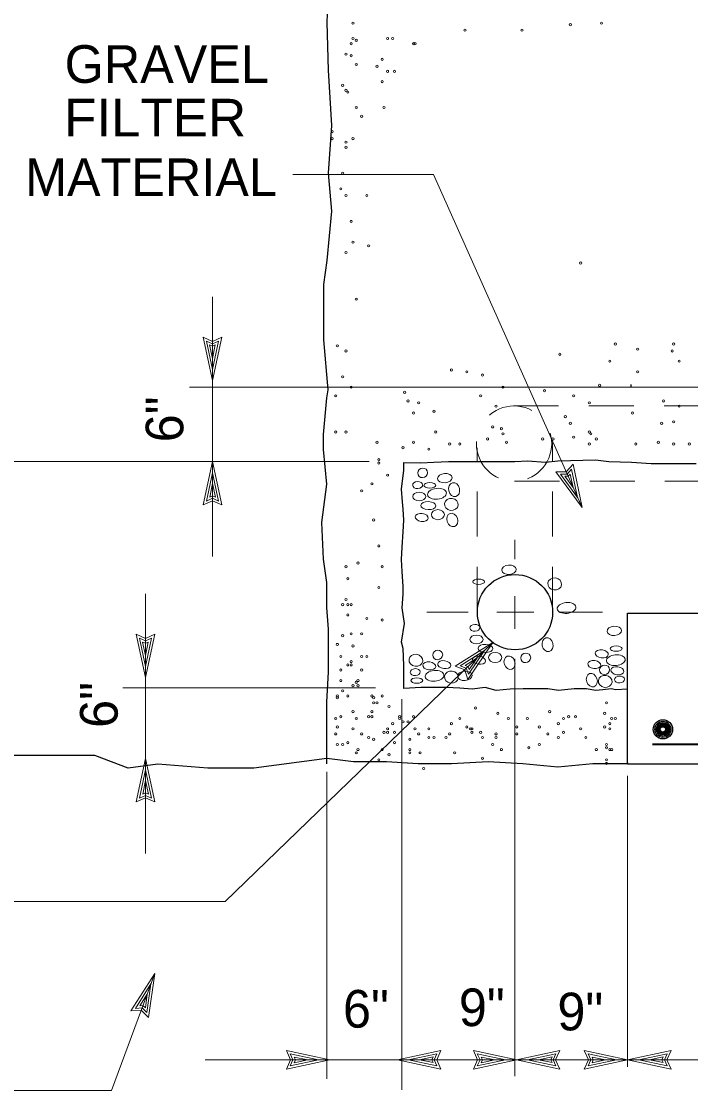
# Model space of a CAD drawing. Extents: x -24.3 to 17.7, y -17.6 to 12.4.
# Drawn here: x -19.213 to -16.992, y -13.602 to -10.053 of the extents above; entities that cross this region are included whole.
import ezdxf
from ezdxf.enums import TextEntityAlignment as Align

# ---------------------------------------------------------------- set-up
doc = ezdxf.new("R2010")
doc.units = 0
doc.header["$LTSCALE"] = 0.05
doc.linetypes.add('MEDIUM_DASHED', pattern=[4.5, 3, -1.5])
doc.layers.add('1', color=7, linetype='Continuous', lineweight=13)

msp = doc.modelspace()

# ---------------------------------------------------------------- linework, layer by layer
at = {"layer": '1'}
for p, q in [((-18.57869, -11.2446), (-18.60969, -11.1006)), ((-18.57869, -11.2446), (-18.54769, -11.1006)), ((-18.57869, -11.2076), (-18.59869, -11.1136)), ((-18.59869, -11.1136), (-18.57869, -11.1226)), ((-18.57869, -11.1716), (-18.58869, -11.1266)), ((-18.58869, -11.1266), (-18.57869, -11.1306)), ((-18.57869, -11.2076), (-18.55869, -11.1136)), ((-18.57869, -11.1226), (-18.55869, -11.1136)), ((-18.57869, -11.1716), (-18.56969, -11.1266)), ((-18.57869, -11.1306), (-18.56969, -11.1266)), ((-16.59669, -11.2666), (-18.65469, -11.2666)), ((-18.05869, -11.5136), (-19.44569, -11.5136)), ((-18.57869, -11.5136), (-18.60969, -11.6576)), ((-18.57869, -11.5136), (-18.54769, -11.6576)), ((-17.35169, -11.6666), (-17.38169, -11.5226)), ((-18.57869, -11.5506), (-18.59869, -11.6446)), ((-18.57869, -11.5506), (-18.55869, -11.6446)), ((-17.36669, -11.6326), (-17.42369, -11.5556)), ((-17.42369, -11.5556), (-17.40169, -11.5556)), ((-17.38169, -11.5996), (-17.40869, -11.5626)), ((-17.40869, -11.5626), (-17.39769, -11.5626)), ((-17.40169, -11.5556), (-17.38669, -11.5386)), ((-17.39769, -11.5626), (-17.39169, -11.5556)), ((-17.38169, -11.5996), (-17.39169, -11.5556)), ((-17.36669, -11.6326), (-17.38669, -11.5386)), ((-18.57869, -11.5866), (-18.58769, -11.6316)), ((-18.57869, -11.5866), (-18.56869, -11.6316)), ((-18.57869, -11.6356), (-18.59869, -11.6446)), ((-18.57869, -11.6276), (-18.58769, -11.6316)), ((-18.56869, -11.6316), (-18.57869, -11.6276)), ((-18.55869, -11.6446), (-18.57869, -11.6356)), ((-17.57569, -11.8376), (-17.57569, -11.7736)), ((-17.57569, -12.0686), (-17.57569, -11.9606)), ((-17.86769, -12.0136), (-17.72969, -12.0136)), ((-17.63469, -12.0136), (-17.51169, -12.0136)), ((-17.42869, -12.0136), (-17.28469, -12.0136)), ((-18.80169, -12.2306), (-18.83269, -12.0866)), ((-18.80169, -12.1936), (-18.82169, -12.0996)), ((-18.82169, -12.0996), (-18.80169, -12.1086)), ((-18.80169, -12.2306), (-18.77069, -12.0866)), ((-18.80169, -12.1936), (-18.78169, -12.0996)), ((-18.80169, -12.1086), (-18.78169, -12.0996)), ((-18.80169, -12.1576), (-18.81169, -12.1126)), ((-18.81169, -12.1126), (-18.80169, -12.1166)), ((-18.80169, -12.1576), (-18.79269, -12.1126)), ((-18.80169, -12.1166), (-18.79269, -12.1126)), ((-17.64869, -12.1146), (-17.77369, -12.1926)), ((-17.67569, -12.1406), (-17.75669, -12.1916)), ((-17.70069, -12.1656), (-17.73969, -12.1906)), ((-17.67569, -12.1406), (-17.72869, -12.2196)), ((-17.70069, -12.1656), (-17.72669, -12.2036)), ((-17.57569, -13.5536), (-17.57569, -12.1686)), ((-17.73669, -12.1996), (-17.75669, -12.1916)), ((-17.73069, -12.1936), (-17.73969, -12.1906)), ((-17.72869, -12.2196), (-17.73669, -12.1996)), ((-17.72669, -12.2036), (-17.73069, -12.1936)), ((-18.03769, -12.2646), (-18.87669, -12.2646)), ((-17.95069, -13.5986), (-17.95069, -12.3026)), ((-18.80169, -12.4996), (-18.83269, -12.6436)), ((-18.80169, -12.4996), (-18.77069, -12.6436)), ((-18.80169, -12.5366), (-18.82169, -12.6306)), ((-18.80169, -12.5366), (-18.78169, -12.6306)), ((-18.19969, -13.5626), (-18.19969, -12.5436)), ((-17.20069, -13.5226), (-17.20069, -12.5566)), ((-18.80169, -12.5726), (-18.81069, -12.6176)), ((-18.80169, -12.5726), (-18.79169, -12.6176)), ((-18.80169, -12.6216), (-18.82169, -12.6306)), ((-18.80169, -12.6136), (-18.81069, -12.6176)), ((-18.79169, -12.6176), (-18.80169, -12.6136)), ((-18.78169, -12.6306), (-18.80169, -12.6216)), ((-18.77069, -13.2126), (-18.84969, -13.3366)), ((-18.78369, -13.2476), (-18.83469, -13.3286)), ((-18.78369, -13.2476), (-18.79669, -13.3426)), ((-18.79569, -13.2816), (-18.81969, -13.3206)), ((-18.79569, -13.2816), (-18.80169, -13.3266)), ((-18.81269, -13.3266), (-18.83469, -13.3286)), ((-18.80969, -13.3196), (-18.81969, -13.3206)), ((-18.79669, -13.3426), (-18.81269, -13.3266)), ((-18.80169, -13.3266), (-18.80969, -13.3196)), ((-18.18969, -13.4996), (-18.33369, -13.4686)), ((-18.22669, -13.4996), (-18.32069, -13.4796)), ((-18.31169, -13.4996), (-18.32069, -13.4796)), ((-17.96469, -13.4996), (-17.82069, -13.4686)), ((-17.92769, -13.4996), (-17.83369, -13.4796)), ((-17.83369, -13.4796), (-17.84269, -13.4996)), ((-17.56869, -13.4996), (-17.71269, -13.4686)), ((-17.60569, -13.4996), (-17.69969, -13.4796)), ((-17.69069, -13.4996), (-17.69969, -13.4796)), ((-17.56969, -13.4996), (-17.42569, -13.4686)), ((-17.53269, -13.4996), (-17.43869, -13.4796)), ((-17.43869, -13.4796), (-17.44769, -13.4996)), ((-17.20069, -13.4996), (-17.34469, -13.4686)), ((-17.23769, -13.4996), (-17.33169, -13.4796)), ((-17.32269, -13.4996), (-17.33169, -13.4796)), ((-17.20069, -13.4996), (-17.05669, -13.4686)), ((-17.16369, -13.4996), (-17.06969, -13.4796)), ((-17.06969, -13.4796), (-17.07869, -13.4996)), ((-18.60369, -13.4996), (-18.18969, -13.4996)), ((-18.18969, -13.4996), (-18.33369, -13.5306)), ((-18.22669, -13.4996), (-18.32069, -13.5196)), ((-18.32069, -13.5196), (-18.31169, -13.4996)), ((-18.26269, -13.4996), (-18.30769, -13.4906)), ((-18.30369, -13.4996), (-18.30769, -13.4906)), ((-18.26269, -13.4996), (-18.30769, -13.5096)), ((-18.30769, -13.5096), (-18.30369, -13.4996)), ((-18.19569, -13.4996), (-17.96469, -13.4996)), ((-17.96469, -13.4996), (-17.56869, -13.4996)), ((-17.96469, -13.4996), (-17.82069, -13.5306)), ((-17.92769, -13.4996), (-17.83369, -13.5196)), ((-17.89169, -13.4996), (-17.84669, -13.4896)), ((-17.89169, -13.4996), (-17.84669, -13.5086)), ((-17.84669, -13.4896), (-17.85069, -13.4996)), ((-17.85069, -13.4996), (-17.84669, -13.5086)), ((-17.84269, -13.4996), (-17.83369, -13.5196)), ((-17.56869, -13.4996), (-17.71269, -13.5306)), ((-17.60569, -13.4996), (-17.69969, -13.5196)), ((-17.69969, -13.5196), (-17.69069, -13.4996)), ((-17.64169, -13.4996), (-17.68669, -13.4906)), ((-17.68269, -13.4996), (-17.68669, -13.4906)), ((-17.64169, -13.4996), (-17.68669, -13.5096)), ((-17.68669, -13.5096), (-17.68269, -13.4996)), ((-17.56969, -13.4996), (-17.20069, -13.4996)), ((-17.56969, -13.4996), (-17.42569, -13.5306)), ((-17.53269, -13.4996), (-17.43869, -13.5196)), ((-17.49669, -13.4996), (-17.45169, -13.4896)), ((-17.49669, -13.4996), (-17.45169, -13.5086)), ((-17.45169, -13.4896), (-17.45569, -13.4996)), ((-17.45569, -13.4996), (-17.45169, -13.5086)), ((-17.44769, -13.4996), (-17.43869, -13.5196)), ((-17.20069, -13.4996), (-17.34469, -13.5306)), ((-17.23769, -13.4996), (-17.33169, -13.5196)), ((-17.33169, -13.5196), (-17.32269, -13.4996)), ((-17.27369, -13.4996), (-17.31869, -13.4906)), ((-17.31469, -13.4996), (-17.31869, -13.4906)), ((-17.27369, -13.4996), (-17.31869, -13.5096)), ((-17.31869, -13.5096), (-17.31469, -13.4996)), ((-17.20069, -13.4996), (-17.05669, -13.5306)), ((-17.16369, -13.4996), (-17.06969, -13.5196)), ((-17.12769, -13.4996), (-17.08269, -13.4896)), ((-17.12769, -13.4996), (-17.08269, -13.5086)), ((-17.08269, -13.4896), (-17.08669, -13.4996)), ((-17.08669, -13.4996), (-17.08269, -13.5086)), ((-17.07869, -13.4996), (-17.06969, -13.5196)), ((-19.30869, -13.6016), (-18.91369, -13.6016))]:
    msp.add_line(p, q, dxfattribs=at)
at = {"layer": '1', "lineweight": 25}
for p, q in [((-17.18969, -11.2576), (-17.18969, -11.2646)), ((-17.20069, -12.0166), (-15.57569, -12.0166)), ((-17.20069, -12.5166), (-17.20069, -12.0166))]:
    msp.add_line(p, q, dxfattribs=at)
at = {"layer": '1', "linetype": 'MEDIUM_DASHED'}
for p, q in [((-17.57969, -11.3286), (-16.55969, -11.3286)), ((-17.44969, -12.0126), (-17.44969, -11.4516)), ((-17.69969, -12.0126), (-17.69969, -11.4686)), ((-17.57669, -11.5786), (-16.69969, -11.5786))]:
    msp.add_line(p, q, dxfattribs=at)
at = {"layer": '1', "lineweight": 35}
msp.add_line((-16.18569, -12.4526), (-17.11869, -12.4526), dxfattribs=at)
at = {"layer": '1', "lineweight": 25}
for points in [[(-18.19969, -12.4996), (-18.44169, -12.5316), (-18.59469, -12.5316), (-18.76069, -12.5176), (-18.85869, -12.5316), (-18.96969, -12.4896), (-19.23369, -12.4896), (-19.35869, -12.4896), (-19.55369, -12.5176), (-19.73469, -12.4896), (-19.92869, -12.4756), (-19.95069, -12.4756), (-19.98469, -12.3086), (-19.97069, -12.0726), (-19.97069, -11.8226), (-19.94269, -11.5586), (-19.97069, -11.3916), (-19.94269, -11.1136), (-19.94269, -10.8626), (-19.94269, -10.7796), (-19.94269, -10.5576), (-19.94269, -10.2796), (-19.94269, -10.0566), (-19.97069, -9.8206)], [(-18.19469, -11.2756), (-18.20969, -11.1096), (-18.20969, -10.9256), (-18.19869, -10.8466), (-18.18269, -10.6826), (-18.19369, -10.5566), (-18.18269, -10.3986), (-18.19369, -10.2146), (-18.19869, -10.0566), (-18.19369, -9.9406), (-18.19369, -9.8546), (-18.06669, -9.8546), (-17.92469, -9.8456), (-17.73569, -9.8616), (-17.57769, -9.8516), (-17.45169, -9.8456), (-17.34569, -9.8456), (-17.21969, -9.8616), (-17.15169, -9.8676), (-17.07869, -9.8596)], [(-18.19969, -12.5166), (-18.19969, -12.4276), (-18.19969, -12.3506), (-18.19969, -12.3116), (-18.19369, -12.2126), (-18.19369, -12.1686), (-18.19369, -12.0696), (-18.19969, -11.9976), (-18.19969, -11.9146), (-18.21069, -11.8376), (-18.21569, -11.7156), (-18.19969, -11.5886), (-18.21069, -11.4736), (-18.21069, -11.4236), (-18.19969, -11.3026), (-18.19469, -11.2756)], [(-17.20069, -12.2696), (-17.23969, -12.2716), (-17.25569, -12.2676), (-17.28269, -12.2716), (-17.30769, -12.2736), (-17.33769, -12.2676), (-17.37769, -12.2676), (-17.43069, -12.2736), (-17.46569, -12.2676), (-17.50169, -12.2676), (-17.54769, -12.2676), (-17.59069, -12.2696), (-17.63769, -12.2736), (-17.67369, -12.2636), (-17.71669, -12.2696), (-17.75769, -12.2656), (-17.80169, -12.2636), (-17.83269, -12.2636), (-17.88769, -12.2636), (-17.94369, -12.2666), (-17.94369, -12.1906), (-17.94569, -12.1346), (-17.95169, -12.1136), (-17.94169, -12.0516), (-17.94969, -11.9996), (-17.94569, -11.9536), (-17.94569, -11.9286), (-17.94969, -11.8786), (-17.95169, -11.8386), (-17.94969, -11.7976), (-17.94569, -11.7466), (-17.94369, -11.7086), (-17.94569, -11.6716), (-17.94769, -11.6476), (-17.95169, -11.6056), (-17.94369, -11.5426), (-17.94369, -11.5166), (-17.88769, -11.5176), (-17.84369, -11.5156), (-17.79569, -11.5136), (-17.74969, -11.5136), (-17.68669, -11.5136), (-17.63369, -11.5136), (-17.57469, -11.5136), (-17.53169, -11.5116), (-17.47369, -11.5156), (-17.43269, -11.5116), (-17.30769, -11.5076), (-17.26269, -11.5136), (-17.18769, -11.5156), (-17.12269, -11.5196), (-17.06169, -11.5196), (-16.97269, -11.5196)], [(-17.20069, -12.5166), (-15.57569, -12.5166), (-15.57569, -12.0166)], [(-17.20069, -12.5136), (-17.20069, -12.5166), (-17.31669, -12.5166), (-17.43269, -12.5276), (-17.54869, -12.5166), (-17.66369, -12.5106), (-17.78569, -12.5166), (-17.89569, -12.5166), (-18.00069, -12.5106), (-18.11069, -12.5106), (-18.19969, -12.4996)]]:
    msp.add_lwpolyline(points, dxfattribs=at)
at = {"layer": '1'}
for points in [[(-18.31169, -10.5606), (-17.84569, -10.5606), (-17.35169, -11.6666), (-17.43869, -11.5476)], [(-18.57869, -11.8286), (-18.57869, -11.5136), (-18.57869, -11.2446), (-18.57869, -10.9666)], [(-18.60969, -11.1006), (-18.57869, -11.1146), (-18.54769, -11.1006)], [(-17.43869, -11.5476), (-17.40469, -11.5476), (-17.38169, -11.5226)], [(-18.54769, -11.6576), (-18.57869, -11.6436), (-18.60969, -11.6576)], [(-18.80169, -12.8146), (-18.80169, -12.4996), (-18.80169, -12.2306), (-18.80169, -11.9526)], [(-18.83269, -12.0866), (-18.80169, -12.1006), (-18.77069, -12.0866)], [(-19.56469, -12.9736), (-18.53669, -12.9736), (-17.64869, -12.1146), (-17.73069, -12.2366)], [(-17.73069, -12.2366), (-17.74169, -12.2046), (-17.77369, -12.1926)], [(-18.77069, -12.6436), (-18.80169, -12.6296), (-18.83269, -12.6436)], [(-18.91469, -13.6016), (-18.77069, -13.2126), (-18.79169, -13.3586)], [(-18.79169, -13.3586), (-18.81569, -13.3346), (-18.84969, -13.3366)], [(-18.33369, -13.5306), (-18.31969, -13.4996), (-18.33369, -13.4686)], [(-17.82069, -13.4686), (-17.83469, -13.4996), (-17.82069, -13.5306)], [(-17.71269, -13.5306), (-17.69869, -13.4996), (-17.71269, -13.4686)], [(-17.42569, -13.4686), (-17.43969, -13.4996), (-17.42569, -13.5306)], [(-17.34469, -13.5306), (-17.33069, -13.4996), (-17.34469, -13.4686)], [(-17.05669, -13.4686), (-17.07069, -13.4996), (-17.05669, -13.5306)], [(-17.20069, -13.4996), (-16.70069, -13.4996), (-16.07569, -13.4996)]]:
    msp.add_lwpolyline(points, dxfattribs=at)
for centre in [(-18.11269, -10.0586), (-17.74069, -10.0816), (-17.55169, -10.0816), (-17.39069, -10.0636), (-17.28769, -10.0586), (-18.11269, -10.1096), (-18.10169, -10.1156), (-17.99769, -10.1096), (-17.98069, -10.1096), (-18.11869, -10.1266), (-17.91169, -10.1266), (-17.90669, -10.1266), (-18.13569, -10.1616), (-18.11869, -10.1666), (-18.01569, -10.1786), (-18.10169, -10.1956), (-18.03269, -10.2016), (-17.99769, -10.2186), (-17.97469, -10.2186), (-18.01569, -10.2526), (-18.14669, -10.2646), (-18.13569, -10.2816), (-18.12969, -10.2876), (-18.10169, -10.3386), (-18.00969, -10.3386), (-18.08369, -10.3676), (-18.18169, -10.4186), (-18.18169, -10.4416), (-18.13569, -10.4536), (-18.13569, -10.4706), (-18.11269, -10.4416), (-18.14669, -10.5566), (-18.15269, -10.6086), (-18.13569, -10.6306), (-18.06669, -10.6306), (-18.11869, -10.7166), (-18.11269, -10.7856), (-18.13569, -10.8196), (-18.06069, -10.7976), (-17.35669, -10.8546), (-18.10169, -10.9746), (-18.16469, -11.1296), (-18.13569, -11.1466), (-17.24169, -11.1236), (-17.16769, -11.1406), (-17.05269, -11.1466), (-17.04769, -11.1236), (-17.42569, -11.1576), (-17.25969, -11.1806), (-17.02969, -11.1806), (-17.78569, -11.2096), (-17.73469, -11.2156), (-17.16769, -11.2156), (-18.14669, -11.2326), (-18.14669, -11.2326), (-17.68269, -11.2266), (-18.11869, -11.2666), (-17.94069, -11.2836), (-17.61469, -11.2666), (-17.47669, -11.2786), (-17.29369, -11.2606), (-18.16969, -11.2956), (-17.92969, -11.3126), (-17.89469, -11.3186), (-17.68869, -11.2956), (-17.37969, -11.2956), (-17.32769, -11.3186), (-17.08169, -11.3126), (-17.91169, -11.3526), (-17.84369, -11.3466), (-17.63769, -11.3296), (-17.18469, -11.3526), (-17.02969, -11.3296), (-17.40769, -11.3646), (-17.39069, -11.3866), (-17.08769, -11.3866), (-17.04769, -11.3816), (-18.16969, -11.4156), (-18.13569, -11.4156), (-17.83769, -11.4156), (-17.64869, -11.3986), (-17.61969, -11.4046), (-17.61469, -11.4216), (-17.32769, -11.4156), (-17.32269, -11.4216), (-18.03269, -11.4496), (-17.91169, -11.4496), (-17.79169, -11.4556), (-17.75769, -11.4556), (-17.66569, -11.4386), (-17.60269, -11.4496), (-17.48269, -11.4386), (-17.44869, -11.4386), (-17.37969, -11.4326), (-17.32769, -11.4556), (-17.30469, -11.4386), (-17.17369, -11.4556), (-17.09869, -11.4496), (-17.04769, -11.4556), (-16.99569, -11.4556), (-17.94669, -11.4676), (-17.86069, -11.4726), (-18.02669, -11.5076), (-18.02669, -11.5186), (-17.99769, -11.5586), (-18.04969, -11.5876), (-18.08369, -11.6106), (-18.04369, -11.7076), (-18.02669, -11.7936), (-18.09569, -11.8506), (-18.13569, -11.8626), (-18.01569, -11.8626), (-18.12969, -11.9026), (-18.02669, -11.9316), (-18.14669, -11.9886), (-18.13569, -11.9716), (-18.12969, -11.9886), (-18.11869, -11.9886), (-18.12969, -12.0226), (-18.06669, -12.0346), (-18.01569, -12.0396), (-18.14669, -12.0916), (-18.11869, -12.0856), (-18.08369, -12.0856), (-18.16469, -12.1206), (-18.11269, -12.1256), (-18.15269, -12.1606), (-18.08369, -12.1606), (-18.06669, -12.1606), (-18.15269, -12.2056), (-18.12969, -12.1886), (-18.11869, -12.1776), (-18.11869, -12.1886), (-18.08369, -12.2056), (-18.15269, -12.2406), (-18.15269, -12.2406), (-18.10169, -12.2466), (-18.09569, -12.2406), (-18.14669, -12.2746), (-18.11269, -12.2576), (-18.09569, -12.2576), (-18.16469, -12.2916), (-18.16469, -12.2976), (-18.12969, -12.2916), (-18.04969, -12.2916), (-18.04369, -12.2976), (-18.04369, -12.3146), (-18.03269, -12.3146), (-18.01569, -12.2916), (-17.27069, -12.3146), (-18.11269, -12.3436), (-18.04969, -12.3436), (-17.99269, -12.3266), (-17.70569, -12.3316), (-17.63169, -12.3496), (-17.45969, -12.3436), (-17.27669, -12.3496), (-18.16969, -12.3666), (-18.15269, -12.3606), (-18.10169, -12.3666), (-18.06069, -12.3606), (-18.04969, -12.3606), (-17.98069, -12.3836), (-17.95769, -12.3606), (-17.95769, -12.3666), (-17.94669, -12.3776), (-17.92969, -12.3776), (-17.91169, -12.3606), (-17.78569, -12.3836), (-17.75769, -12.3666), (-17.59669, -12.3666), (-17.53369, -12.3666), (-17.43069, -12.3836), (-17.41369, -12.3666), (-17.39669, -12.3606), (-17.37369, -12.3606), (-17.25969, -12.3836), (-17.25369, -12.3666), (-17.24169, -12.3666), (-18.16969, -12.4176), (-18.16469, -12.3946), (-18.11269, -12.4006), (-18.08369, -12.4176), (-18.00969, -12.4126), (-17.99769, -12.4006), (-17.99769, -12.4126), (-17.97469, -12.4126), (-17.90669, -12.4006), (-17.89469, -12.4176), (-17.86069, -12.4006), (-17.79169, -12.4176), (-17.73469, -12.3946), (-17.72269, -12.4006), (-17.71769, -12.4006), (-17.71769, -12.4126), (-17.68869, -12.4126), (-17.63769, -12.4176), (-17.56869, -12.3946), (-17.56869, -12.4176), (-17.49369, -12.3946), (-17.46569, -12.4176), (-17.41369, -12.4126), (-17.35669, -12.4006), (-17.27669, -12.3946), (-17.25969, -12.4006), (-18.16469, -12.4526), (-18.14669, -12.4526), (-18.12969, -12.4466), (-18.06069, -12.4296), (-18.04369, -12.4356), (-17.97469, -12.4466), (-17.92369, -12.4356), (-17.92369, -12.4356), (-17.86069, -12.4296), (-17.84369, -12.4296), (-17.80369, -12.4296), (-17.68269, -12.4296), (-17.64869, -12.4526), (-17.63769, -12.4296), (-17.49369, -12.4526), (-17.43069, -12.4296), (-17.33969, -12.4296), (-17.27069, -12.4526), (-18.10169, -12.4806), (-18.09569, -12.4696), (-18.01569, -12.4696), (-17.99269, -12.4866), (-17.92369, -12.4696), (-17.92369, -12.4806), (-17.88969, -12.4806), (-17.77469, -12.4806), (-17.61969, -12.4696), (-17.52869, -12.4636), (-17.30469, -12.4696), (-17.27069, -12.4636), (-17.25969, -12.4696), (-17.25369, -12.4696), (-18.02669, -12.5036), (-17.68269, -12.4986), (-17.27069, -12.5036), (-17.27069, -12.5156), (-17.87769, -12.5326)]:
    msp.add_circle(centre, 0.00361, dxfattribs=at)
at = {"layer": '1', "linetype": 'MEDIUM_DASHED'}
msp.add_circle((-17.57786, -11.45406), 0.125, dxfattribs=at)
at = {"layer": '1', "lineweight": 25}
for centre, radius in [((-17.57461, -12.01363), 0.125), ((-17.08354, -12.40251), 0.0319), ((-17.08354, -12.40251), 0.02658), ((-17.08354, -12.40251), 0.02215), ((-17.08354, -12.40251), 0.01846), ((-17.08354, -12.40251), 0.01538), ((-17.08354, -12.40251), 0.01282), ((-17.08354, -12.40251), 0.01068), ((-17.08354, -12.40251), 0.0089)]:
    msp.add_circle(centre, radius, dxfattribs=at)
at = {"layer": '1'}
for centre, major_axis, ratio in [((-17.88118, -11.55114), (0.01537, 0.00658), 0.943549), ((-17.80769, -11.56874), (-0.024, -0.00161), 0.646571), ((-17.89775, -11.59153), (0.01656, 0.00102), 0.695424), ((-17.85739, -11.59255), (0.01967, 0), 0.453554), ((-17.83358, -11.62053), (0.03106, 0.0031), 0.576005), ((-17.77662, -11.60705), (0.00519, -0.02279), 0.773526), ((-17.89258, -11.62985), (0.02173, 0), 0.668043), ((-17.78594, -11.6557), (0.02279, -0.0031), 0.872178), ((-17.86256, -11.65984), (0.02483, -0.00104), 0.540552), ((-17.83046, -11.68989), (0.02173, 0), 0.771092), ((-17.88431, -11.6992), (0.02175, -0.0031), 0.60385), ((-17.78285, -11.70749), (0.00725, -0.02173), 0.776129), ((-17.59469, -11.87274), (-0.024, -0.00161), 0.646571), ((-17.69539, -11.91255), (0.01967, 0), 0.453554), ((-17.44294, -11.9197), (0.02279, -0.0031), 0.872178), ((-17.40358, -11.99953), (0.03106, 0.0031), 0.576005), ((-17.70775, -12.06553), (0.01656, 0.00102), 0.695424), ((-17.24515, -12.07557), (-0.024, -0.00161), 0.646571), ((-17.70258, -12.10385), (0.02173, 0), 0.668043), ((-17.46662, -12.12105), (0.00519, -0.02279), 0.773526), ((-17.83127, -12.15554), (0.01537, 0.00658), 0.943549), ((-17.67256, -12.13384), (0.02483, -0.00104), 0.540552), ((-17.28657, -12.15215), (0.02175, -0.0031), 0.60385), ((-17.2389, -12.13455), (0.01967, 0), 0.453554), ((-17.90373, -12.17315), (0.02279, -0.0031), 0.872178), ((-17.80956, -12.18765), (0.02175, -0.0031), 0.60385), ((-17.69431, -12.1732), (0.02175, -0.0031), 0.60385), ((-17.64046, -12.16389), (0.02173, 0), 0.771092), ((-17.59285, -12.18149), (0.00725, -0.02173), 0.776129), ((-17.53918, -12.16514), (0.01537, 0.00658), 0.943549), ((-17.3114, -12.18736), (0.02175, -0.0031), 0.60385), ((-17.23997, -12.1729), (0.03106, 0.0031), 0.576005), ((-17.90583, -12.21252), (0.01656, 0.00102), 0.695424), ((-17.85927, -12.19177), (0.02175, -0.0031), 0.60385), ((-17.84166, -12.22494), (0.03106, 0.0031), 0.576005), ((-17.78573, -12.22906), (0.02279, -0.0031), 0.872178), ((-17.74123, -12.22494), (-0.024, -0.00161), 0.646571), ((-17.27724, -12.20496), (0.01537, 0.00658), 0.943549), ((-17.23478, -12.20807), (0.02175, -0.0031), 0.60385), ((-17.90064, -12.24046), (0.01967, 0), 0.453554), ((-17.31965, -12.23915), (0.00725, -0.02173), 0.776129), ((-17.27511, -12.24327), (0.02279, -0.0031), 0.872178), ((-17.22751, -12.23711), (0.01656, 0.00102), 0.695424)]:
    msp.add_ellipse(centre, major_axis=major_axis, ratio=ratio, dxfattribs=at)

# ---------------------------------------------------------------- texts
for s, p in [('GRAVEL', (-18.73069, -10.2566)), ('MATERIAL', (-18.78319, -10.6326))]:
    msp.add_text(s, height=0.125, dxfattribs=at).set_placement(p, align=Align.CENTER)
at = {"layer": '1', "width": 1.05}
msp.add_text('FILTER', height=0.125, dxfattribs=at).set_placement((-18.76919, -10.4346), align=Align.CENTER)
at = {"layer": '1'}
for p in [(-18.67569, -11.4496), (-18.89369, -12.3976)]:
    msp.add_text('6"', height=0.125, rotation=90, dxfattribs=at).set_placement(p)
msp.add_text('6"', height=0.125, dxfattribs=at).set_placement((-18.14569, -13.3926))
for p in [(-17.60869, -13.3876), (-17.28169, -13.4016)]:
    msp.add_text('9"', height=0.125, dxfattribs=at).set_placement(p, align=Align.RIGHT)

doc.saveas('drawing.dxf')
